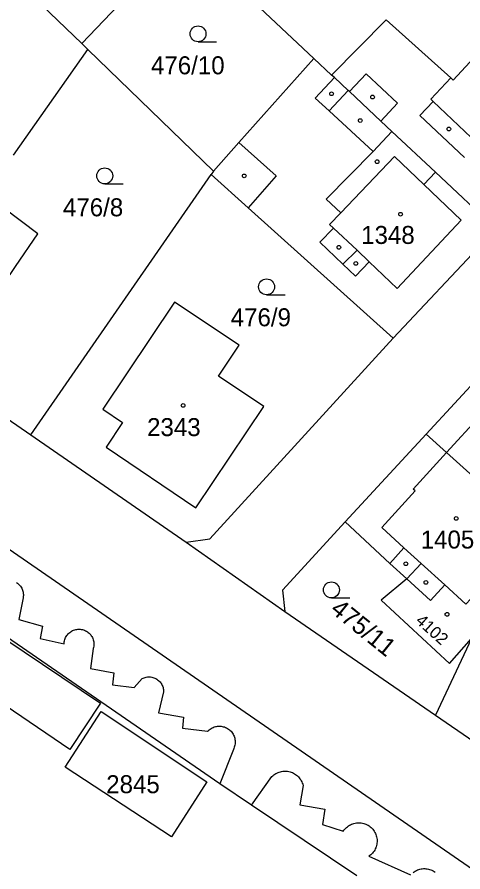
# Model space of a CAD drawing. Extents: x -679220 to -673243, y -1075091 to -1066557.
# Drawn here: x -675741.4 to -675699.3, y -1072325.9 to -1072245.2 of the extents above; entities that cross this region are included whole.
import ezdxf

# ---------------------------------------------------------------- set-up
doc = ezdxf.new("R2010")
doc.units = 0
for name, color, linetype in [('Hranice parcel', 7, 'Continuous'), ('Parcelní čísla', 7, 'Continuous'), ('Vnitřní kresba', 7, 'Continuous'), ('Značky budov', 7, 'Continuous'), ('Značky kultur', 7, 'Continuous')]:
    doc.layers.add(name, color=color, linetype=linetype)

msp = doc.modelspace()

# ---------------------------------------------------------------- linework, layer by layer
at = {"layer": 'Hranice parcel'}
for p, q in [((-675745.72, -1072237.63), (-675735.32, -1072247.67)), ((-675713.39, -1072249.07), (-675725.65, -1072237.57)), ((-675735.32, -1072247.67), (-675727.35, -1072239.34)), ((-675734.75, -1072248.23), (-675735.32, -1072247.67)), ((-675741.76, -1072258.21), (-675734.75, -1072248.23)), ((-675722.86, -1072259.71), (-675734.75, -1072248.23)), ((-675711.73, -1072250.64), (-675713.39, -1072249.07)), ((-675740.12, -1072284.65), (-675723.09, -1072260.04)), ((-675722.86, -1072259.71), (-675723.09, -1072260.04)), ((-675705.9, -1072275.51), (-675696.22, -1072265.18)), ((-675753.67, -1072275.25), (-675740.12, -1072284.65)), ((-675695.05, -1072276.14), (-675702.81, -1072284.58)), ((-675740.12, -1072284.65), (-675725.45, -1072294.77)), ((-675702.81, -1072284.58), (-675710.43, -1072292.87)), ((-675725.45, -1072294.77), (-675716.14, -1072301.34)), ((-675704.61, -1072298.25), (-675707.06, -1072300.26)), ((-675707.06, -1072300.26), (-675700.58, -1072306.26)), ((-675716.14, -1072301.34), (-675701.9, -1072311.14)), ((-675698.51, -1072303.87), (-675701.9, -1072311.14)), ((-675700.58, -1072306.26), (-675698.51, -1072303.87)), ((-675701.9, -1072311.14), (-675698.3, -1072313.6))]:
    msp.add_line(p, q, dxfattribs=at)
for points in [[(-675675.24, -1072344.8), (-675677.06, -1072343.56), (-675675.65, -1072341.45), (-675809.62, -1072248.86), (-675810.47, -1072252.39), (-675814.41, -1072249.48), (-675828.02, -1072240.66), (-675831.19, -1072238.38)], [(-675695.17, -1072245.64), (-675695.53, -1072246.03), (-675700.26, -1072251.11), (-675700.48, -1072250.91), (-675706.57, -1072245.42), (-675711.73, -1072250.64)], [(-675713.39, -1072249.07), (-675720.47, -1072257.02), (-675722.86, -1072259.71)], [(-675696.22, -1072265.18), (-675701.93, -1072259.82), (-675706.03, -1072255.98), (-675707.09, -1072254.99), (-675710.05, -1072252.21), (-675710.16, -1072252.11), (-675711.46, -1072250.88), (-675711.73, -1072250.64)], [(-675723.09, -1072260.04), (-675719.59, -1072263.18), (-675705.9, -1072275.51)], [(-675751.96, -1072272.79), (-675747.81, -1072275.65), (-675744.69, -1072271.12), (-675743.69, -1072271.81), (-675741.58, -1072268.74), (-675739.46, -1072265.66), (-675744.38, -1072261.95)], [(-675709.33, -1072326.32), (-675719.29, -1072319.62), (-675722.28, -1072317.61), (-675767.55, -1072286.39), (-675771.79, -1072283.55), (-675799.8, -1072264.22)], [(-675720.46, -1072276.18), (-675726.55, -1072272.1), (-675733.33, -1072282.22), (-675731.46, -1072283.47), (-675733.02, -1072285.79), (-675724.54, -1072291.53), (-675718.12, -1072281.95), (-675722.4, -1072279.08), (-675720.46, -1072276.18)], [(-675725.45, -1072294.77), (-675723.21, -1072294.48), (-675705.9, -1072275.51)], [(-675690.86, -1072295.31), (-675700.88, -1072286.3), (-675702.81, -1072284.58)], [(-675710.43, -1072292.87), (-675716.35, -1072299.31), (-675716.14, -1072301.34)], [(-675710.43, -1072292.87), (-675706.23, -1072296.78), (-675704.61, -1072298.25)], [(-675754.77, -1072303.57), (-675761.2, -1072299.24), (-675757.12, -1072294.14), (-675733.54, -1072309.98), (-675736.43, -1072314.38), (-675754.01, -1072302.43), (-675754.77, -1072303.57)], [(-675704.61, -1072298.25), (-675702.38, -1072300.29), (-675701.04, -1072298.81), (-675699.04, -1072300.63), (-675698.59, -1072300.14), (-675696.67, -1072301.8)], [(-675733.47, -1072310.79), (-675723.51, -1072317.42), (-675726.83, -1072322.61), (-675736.89, -1072316.04), (-675733.47, -1072310.79)]]:
    msp.add_lwpolyline(points, dxfattribs=at)
at = {"layer": 'Vnitřní kresba'}
for p, q in [((-675713.28, -1072252.82), (-675711.46, -1072250.88)), ((-675710.05, -1072252.21), (-675708.47, -1072250.53)), ((-675708.47, -1072250.53), (-675705.51, -1072253.31)), ((-675700.48, -1072250.91), (-675702.36, -1072252.92)), ((-675711.94, -1072254.01), (-675713.28, -1072252.82)), ((-675711.94, -1072254.01), (-675710.16, -1072252.11)), ((-675705.51, -1072253.31), (-675707.09, -1072254.99)), ((-675702.14, -1072253.13), (-675703.39, -1072254.47)), ((-675702.36, -1072252.92), (-675702.14, -1072253.13)), ((-675702.14, -1072253.13), (-675697.94, -1072257.12)), ((-675707.81, -1072257.88), (-675711.94, -1072254.01)), ((-675703.39, -1072254.47), (-675699.18, -1072258.43)), ((-675706.03, -1072255.98), (-675707.81, -1072257.88)), ((-675720.47, -1072257.02), (-675716.97, -1072260.16)), ((-675712.24, -1072262.36), (-675707.81, -1072257.88)), ((-675710.86, -1072263.67), (-675705.8, -1072258.34)), ((-675705.8, -1072258.34), (-675703.03, -1072260.97)), ((-675703.03, -1072260.97), (-675701.93, -1072259.82)), ((-675716.97, -1072260.16), (-675719.59, -1072263.18)), ((-675703.03, -1072260.97), (-675699.48, -1072264.35)), ((-675710.86, -1072263.67), (-675712.24, -1072262.36)), ((-675711.92, -1072264.77), (-675710.86, -1072263.67)), ((-675711.56, -1072265.11), (-675711.92, -1072264.77)), ((-675705.55, -1072270.81), (-675699.48, -1072264.35)), ((-675712.82, -1072266.44), (-675711.56, -1072265.11)), ((-675709.32, -1072267.2), (-675711.56, -1072265.11)), ((-675712.82, -1072266.44), (-675710.67, -1072268.5)), ((-675710.67, -1072268.5), (-675709.32, -1072267.2)), ((-675709.32, -1072267.2), (-675708.17, -1072268.3)), ((-675710.67, -1072268.5), (-675709.46, -1072269.65)), ((-675709.46, -1072269.65), (-675708.17, -1072268.3)), ((-675708.17, -1072268.3), (-675705.55, -1072270.81)), ((-675700.88, -1072286.3), (-675697.71, -1072282.83)), ((-675704.03, -1072289.76), (-675700.88, -1072286.3)), ((-675706.98, -1072293.39), (-675703.83, -1072289.94)), ((-675703.83, -1072289.94), (-675704.03, -1072289.76)), ((-675706.98, -1072293.39), (-675704.89, -1072295.3)), ((-675706.23, -1072296.78), (-675704.89, -1072295.3)), ((-675704.89, -1072295.3), (-675703.27, -1072296.78)), ((-675703.27, -1072296.78), (-675704.61, -1072298.25)), ((-675703.27, -1072296.78), (-675701.04, -1072298.81)), ((-675740.85, -1072300.03), (-675741.25, -1072302.08)), ((-675741.25, -1072302.08), (-675739.02, -1072302.72)), ((-675739.02, -1072302.72), (-675739.23, -1072303.88)), ((-675739.23, -1072303.88), (-675736.98, -1072304.4)), ((-675734.22, -1072304.82), (-675734.48, -1072306.73)), ((-675734.48, -1072306.73), (-675732.29, -1072307.13)), ((-675732.29, -1072307.13), (-675732.42, -1072308.25)), ((-675730.35, -1072308.5), (-675729.6, -1072307.67)), ((-675732.42, -1072308.25), (-675730.35, -1072308.5)), ((-675727.59, -1072308.92), (-675728.08, -1072310.91)), ((-675728.08, -1072310.91), (-675725.72, -1072311.33)), ((-675725.72, -1072311.33), (-675725.8, -1072312.36)), ((-675725.8, -1072312.36), (-675723.43, -1072312.65)), ((-675721, -1072314.36), (-675722.28, -1072317.61)), ((-675719.29, -1072319.62), (-675717.36, -1072316.93)), ((-675714.42, -1072317.76), (-675714.72, -1072319.59)), ((-675714.72, -1072319.59), (-675712.35, -1072320.01)), ((-675712.35, -1072320.01), (-675712.59, -1072321.47)), ((-675712.59, -1072321.47), (-675710.62, -1072322.1)), ((-675708.21, -1072324.46), (-675704.27, -1072326.22))]:
    msp.add_line(p, q, dxfattribs=at)
for points in [[(-675741.476, -1072298.606), (-675741.39, -1072298.663), (-675741.308, -1072298.726), (-675741.232, -1072298.796), (-675741.161, -1072298.871), (-675741.095, -1072298.952), (-675741.037, -1072299.037), (-675740.984, -1072299.126), (-675740.939, -1072299.219), (-675740.901, -1072299.316), (-675740.871, -1072299.414), (-675740.848, -1072299.515), (-675740.832, -1072299.618), (-675740.825, -1072299.721), (-675740.825, -1072299.825), (-675740.834, -1072299.928), (-675740.85, -1072300.03)], [(-675736.98, -1072304.4), (-675736.975, -1072304.295), (-675736.962, -1072304.191), (-675736.942, -1072304.088), (-675736.914, -1072303.987), (-675736.878, -1072303.889), (-675736.835, -1072303.793), (-675736.786, -1072303.7), (-675736.729, -1072303.612), (-675736.666, -1072303.528), (-675736.597, -1072303.449), (-675736.523, -1072303.375), (-675736.443, -1072303.308), (-675736.358, -1072303.246), (-675736.269, -1072303.19), (-675736.176, -1072303.142), (-675736.08, -1072303.1), (-675735.981, -1072303.066), (-675735.879, -1072303.039), (-675735.776, -1072303.02), (-675735.672, -1072303.009), (-675735.567, -1072303.005), (-675735.462, -1072303.009), (-675735.358, -1072303.021), (-675735.255, -1072303.041), (-675735.154, -1072303.068), (-675735.055, -1072303.103), (-675734.959, -1072303.145), (-675734.866, -1072303.193), (-675734.777, -1072303.249), (-675734.693, -1072303.311), (-675734.613, -1072303.38), (-675734.539, -1072303.454), (-675734.47, -1072303.533), (-675734.408, -1072303.617), (-675734.352, -1072303.706), (-675734.302, -1072303.798), (-675734.26, -1072303.894), (-675734.225, -1072303.993), (-675734.197, -1072304.094), (-675734.177, -1072304.197), (-675734.165, -1072304.301), (-675734.161, -1072304.406), (-675734.164, -1072304.511), (-675734.175, -1072304.615), (-675734.194, -1072304.719), (-675734.22, -1072304.82)], [(-675729.6, -1072307.67), (-675729.508, -1072307.625), (-675729.413, -1072307.588), (-675729.316, -1072307.557), (-675729.216, -1072307.534), (-675729.115, -1072307.518), (-675729.013, -1072307.51), (-675728.911, -1072307.51), (-675728.809, -1072307.517), (-675728.708, -1072307.532), (-675728.609, -1072307.554), (-675728.511, -1072307.584), (-675728.416, -1072307.621), (-675728.323, -1072307.665), (-675728.235, -1072307.715), (-675728.15, -1072307.773), (-675728.07, -1072307.836), (-675727.995, -1072307.905), (-675727.925, -1072307.98), (-675727.861, -1072308.059), (-675727.803, -1072308.143), (-675727.751, -1072308.231), (-675727.706, -1072308.323), (-675727.668, -1072308.418), (-675727.638, -1072308.516), (-675727.615, -1072308.615), (-675727.599, -1072308.716), (-675727.591, -1072308.818), (-675727.59, -1072308.92)], [(-675723.43, -1072312.65), (-675723.354, -1072312.573), (-675723.273, -1072312.502), (-675723.187, -1072312.437), (-675723.096, -1072312.378), (-675723.002, -1072312.326), (-675722.904, -1072312.281), (-675722.803, -1072312.243), (-675722.699, -1072312.213), (-675722.594, -1072312.19), (-675722.487, -1072312.174), (-675722.38, -1072312.167), (-675722.272, -1072312.167), (-675722.164, -1072312.175), (-675722.057, -1072312.19), (-675721.952, -1072312.214), (-675721.848, -1072312.244), (-675721.748, -1072312.283), (-675721.65, -1072312.328), (-675721.555, -1072312.38), (-675721.465, -1072312.439), (-675721.379, -1072312.504), (-675721.298, -1072312.575), (-675721.222, -1072312.652), (-675721.152, -1072312.734), (-675721.088, -1072312.821), (-675721.031, -1072312.913), (-675720.98, -1072313.008), (-675720.936, -1072313.107), (-675720.9, -1072313.208), (-675720.871, -1072313.312), (-675720.849, -1072313.418), (-675720.835, -1072313.525), (-675720.829, -1072313.632), (-675720.831, -1072313.74), (-675720.84, -1072313.848), (-675720.857, -1072313.954), (-675720.882, -1072314.059), (-675720.914, -1072314.162), (-675720.953, -1072314.263), (-675721, -1072314.36)], [(-675717.36, -1072316.93), (-675717.275, -1072316.85), (-675717.186, -1072316.777), (-675717.091, -1072316.709), (-675716.993, -1072316.648), (-675716.89, -1072316.593), (-675716.784, -1072316.545), (-675716.675, -1072316.505), (-675716.564, -1072316.472), (-675716.451, -1072316.446), (-675716.336, -1072316.428), (-675716.221, -1072316.417), (-675716.104, -1072316.414), (-675715.988, -1072316.419), (-675715.873, -1072316.432), (-675715.759, -1072316.452), (-675715.646, -1072316.48), (-675715.535, -1072316.515), (-675715.427, -1072316.558), (-675715.322, -1072316.607), (-675715.221, -1072316.664), (-675715.123, -1072316.727), (-675715.03, -1072316.796), (-675714.942, -1072316.872), (-675714.859, -1072316.953), (-675714.781, -1072317.04), (-675714.709, -1072317.131), (-675714.644, -1072317.227), (-675714.585, -1072317.327), (-675714.533, -1072317.431), (-675714.488, -1072317.538), (-675714.45, -1072317.648), (-675714.42, -1072317.76)], [(-675710.62, -1072322.1), (-675710.555, -1072322.004), (-675710.484, -1072321.912), (-675710.406, -1072321.825), (-675710.323, -1072321.743), (-675710.235, -1072321.668), (-675710.141, -1072321.598), (-675710.044, -1072321.535), (-675709.942, -1072321.479), (-675709.837, -1072321.429), (-675709.728, -1072321.387), (-675709.617, -1072321.352), (-675709.504, -1072321.325), (-675709.389, -1072321.306), (-675709.273, -1072321.294), (-675709.157, -1072321.29), (-675709.041, -1072321.294), (-675708.925, -1072321.305), (-675708.81, -1072321.325), (-675708.697, -1072321.352), (-675708.586, -1072321.387), (-675708.478, -1072321.429), (-675708.372, -1072321.478), (-675708.271, -1072321.535), (-675708.173, -1072321.598), (-675708.08, -1072321.667), (-675707.991, -1072321.743), (-675707.908, -1072321.824), (-675707.831, -1072321.911), (-675707.759, -1072322.003), (-675707.694, -1072322.099), (-675707.636, -1072322.2), (-675707.584, -1072322.304), (-675707.54, -1072322.412), (-675707.503, -1072322.522), (-675707.473, -1072322.635), (-675707.451, -1072322.749), (-675707.437, -1072322.864), (-675707.431, -1072322.981), (-675707.432, -1072323.097), (-675707.442, -1072323.213), (-675707.459, -1072323.328), (-675707.484, -1072323.442), (-675707.516, -1072323.553), (-675707.556, -1072323.663), (-675707.603, -1072323.769), (-675707.657, -1072323.872), (-675707.718, -1072323.971), (-675707.786, -1072324.066), (-675707.86, -1072324.156), (-675707.939, -1072324.24), (-675708.025, -1072324.32), (-675708.115, -1072324.393), (-675708.21, -1072324.46)], [(-675704.015, -1072325.983), (-675703.92, -1072325.916), (-675703.821, -1072325.855), (-675703.718, -1072325.801), (-675703.612, -1072325.754), (-675703.502, -1072325.714), (-675703.391, -1072325.682), (-675703.277, -1072325.657), (-675703.162, -1072325.64), (-675703.046, -1072325.631), (-675702.93, -1072325.629), (-675702.814, -1072325.635), (-675702.699, -1072325.649), (-675702.584, -1072325.67), (-675702.472, -1072325.699), (-675702.362, -1072325.735), (-675702.254, -1072325.779), (-675702.149, -1072325.83), (-675702.048, -1072325.888), (-675701.952, -1072325.952)]]:
    msp.add_lwpolyline(points, dxfattribs=at)
at = {"layer": 'Značky budov'}
for centre in [(-675711.727, -1072252.409), (-675707.857, -1072252.719), (-675709.017, -1072254.939), (-675700.647, -1072255.739), (-675707.427, -1072258.829), (-675719.977, -1072260.169), (-675705.217, -1072263.789), (-675711.037, -1072266.919), (-675709.437, -1072268.439), (-675725.747, -1072281.859), (-675699.957, -1072292.539), (-675704.717, -1072296.819), (-675702.817, -1072298.579), (-675700.827, -1072301.599)]:
    msp.add_circle(centre, 0.175, dxfattribs=at)
at = {"layer": 'Značky kultur'}
for p, q in [((-675724.333, -1072247.5), (-675722.583, -1072247.5)), ((-675733.143, -1072260.92), (-675731.393, -1072260.92)), ((-675717.863, -1072271.4), (-675716.113, -1072271.4)), ((-675711.743, -1072300.04), (-675709.993, -1072300.04))]:
    msp.add_line(p, q, dxfattribs=at)
for centre in [(-675724.333, -1072246.75), (-675733.143, -1072260.17), (-675717.863, -1072270.65), (-675711.743, -1072299.29)]:
    msp.add_circle(centre, 0.75, dxfattribs=at)

# ---------------------------------------------------------------- texts
at = {"layer": 'Parcelní čísla'}
for s, p in [('476/10', (-675728.777, -1072250.57)), ('476/8', (-675737.088, -1072263.989)), ('1348', (-675708.934, -1072266.6)), ('476/9', (-675721.248, -1072274.38)), ('2343', (-675729.144, -1072284.759)), ('1405', (-675703.314, -1072295.38)), ('2845', (-675733.004, -1072318.499))]:
    msp.add_text(s, height=1.7, dxfattribs=at).set_placement(p)
for s, height, rotation, p in [('475/11', 1.7, 321, (-675711.942, -1072301.326)), ('4102', 1.139, 318, (-675703.871, -1072302.319))]:
    msp.add_text(s, height=height, rotation=rotation, dxfattribs=at).set_placement(p)

doc.saveas('drawing.dxf')
